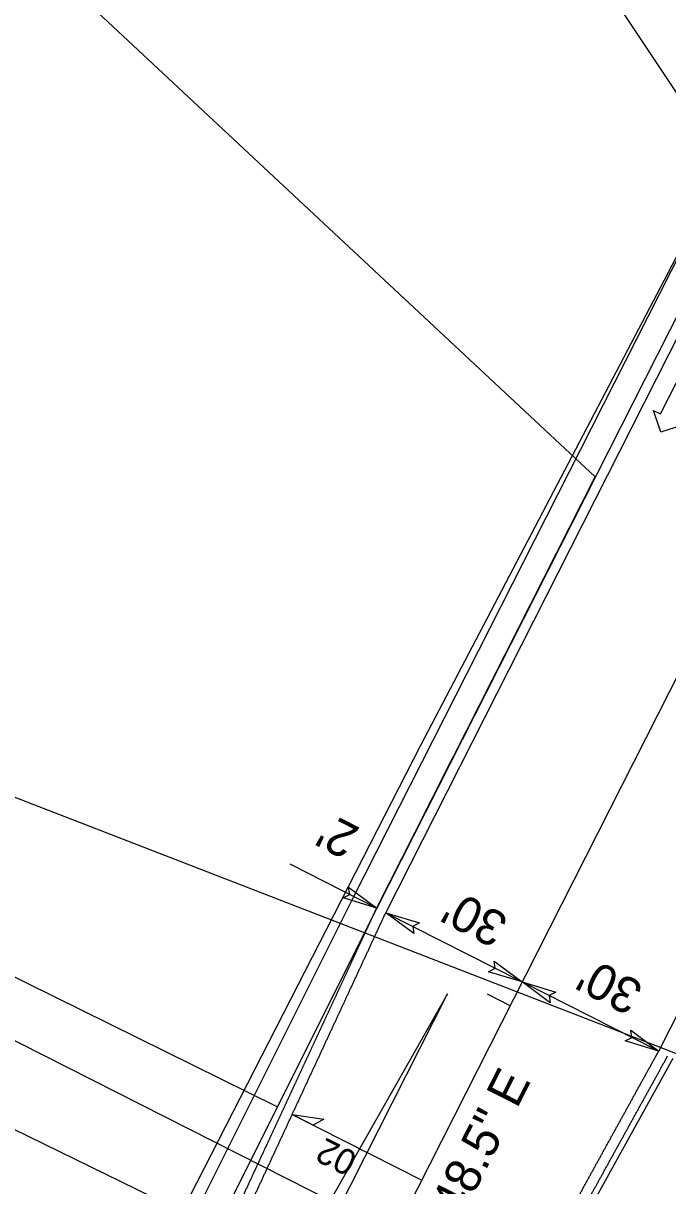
# Model space of a CAD drawing. Extents: x 1974386 to 1979988, y 776712 to 784860.
# Drawn here: x 1977801.6 to 1977928, y 782158.9 to 782386.9 of the extents above; entities that cross this region are included whole.
import ezdxf

# ---------------------------------------------------------------- set-up
doc = ezdxf.new("R2010")
doc.units = 0
for name, color, linetype in [('Prop Conc 2ft 6in Curb and Gutter', 7, 'Continuous'), ('Prop Conc 4in Sidewalk', 7, 'Continuous'), ('Prop Dimension', 7, 'Continuous'), ('Prop Dimension Text', 7, 'Continuous'), ('Prop DSN Text', 7, 'Continuous'), ('Prop EOT', 7, 'Continuous'), ('Prop Guardrail', 7, 'Continuous'), ('Prop Horizontal Alignment', 7, 'Continuous'), ('Prop Horizontal Alignment Direction Label', 7, 'Continuous'), ('Prop Horizontal Alignment Tick Small', 7, 'Continuous'), ('Prop Lane Arrow CELL', 7, 'Continuous'), ('Prop Superelevation  Arrow CELL', 7, 'Continuous'), ('Prop Superelevation Label', 7, 'Continuous'), ('Prop Terminator CELL', 7, 'Continuous'), ('Scratch_Level_1', 7, 'Continuous'), ('Sheet Layout Plan Border', 7, 'Continuous')]:
    doc.layers.add(name, color=color, linetype=linetype)

msp = doc.modelspace()

# ---------------------------------------------------------------- linework, layer by layer
at = {"layer": 'Prop Conc 2ft 6in Curb and Gutter'}
for p, q in [((1977870.83, 782213.26), (1977913.74, 782297.93)), ((1977870.89, 782213.38), (1977885.51, 782242.22))]:
    msp.add_line(p, q, dxfattribs=at)
msp.add_open_spline([(1977849.69, 782167.68), (1977849.78, 782167.88), (1977849.88, 782168.09), (1977849.97, 782168.29), (1977850.07, 782168.5), (1977850.16, 782168.7), (1977850.26, 782168.91), (1977850.36, 782169.12), (1977850.45, 782169.32), (1977850.55, 782169.53), (1977850.64, 782169.73), (1977850.74, 782169.94), (1977850.83, 782170.14), (1977850.93, 782170.35), (1977851.02, 782170.55), (1977851.12, 782170.76), (1977851.21, 782170.97), (1977851.31, 782171.17), (1977851.4, 782171.38), (1977851.5, 782171.58), (1977851.59, 782171.79), (1977851.69, 782171.99), (1977851.79, 782172.2), (1977851.88, 782172.4), (1977851.98, 782172.61), (1977852.07, 782172.82), (1977852.17, 782173.02), (1977852.26, 782173.23), (1977852.36, 782173.43), (1977852.45, 782173.64), (1977852.55, 782173.84), (1977852.64, 782174.05), (1977852.74, 782174.25), (1977852.83, 782174.46), (1977852.93, 782174.67), (1977853.03, 782174.87), (1977853.12, 782175.08), (1977853.22, 782175.28), (1977853.31, 782175.49), (1977853.41, 782175.69), (1977853.5, 782175.9), (1977853.6, 782176.1), (1977853.69, 782176.31), (1977853.79, 782176.52), (1977853.88, 782176.72), (1977853.98, 782176.93), (1977854.07, 782177.13), (1977854.17, 782177.34), (1977854.26, 782177.54), (1977854.36, 782177.75), (1977854.46, 782177.95), (1977854.55, 782178.16), (1977854.65, 782178.37), (1977854.74, 782178.57), (1977854.84, 782178.78), (1977854.93, 782178.98), (1977855.03, 782179.19), (1977855.12, 782179.39), (1977855.22, 782179.6), (1977855.31, 782179.8), (1977855.41, 782180.01), (1977855.5, 782180.22), (1977855.6, 782180.42), (1977855.69, 782180.63), (1977855.79, 782180.83), (1977855.89, 782181.04), (1977855.98, 782181.24), (1977856.08, 782181.45), (1977856.17, 782181.65), (1977856.27, 782181.86), (1977856.36, 782182.07), (1977856.46, 782182.27), (1977856.55, 782182.48), (1977856.65, 782182.68), (1977856.74, 782182.89), (1977856.84, 782183.09), (1977856.93, 782183.3), (1977857.03, 782183.5), (1977857.13, 782183.71), (1977857.22, 782183.92), (1977857.32, 782184.12), (1977857.41, 782184.33), (1977857.51, 782184.53), (1977857.6, 782184.74), (1977857.7, 782184.94), (1977857.79, 782185.15), (1977857.89, 782185.35), (1977857.98, 782185.56), (1977858.08, 782185.77), (1977858.17, 782185.97), (1977858.27, 782186.18), (1977858.36, 782186.38), (1977858.46, 782186.59), (1977858.56, 782186.79), (1977858.65, 782187), (1977858.75, 782187.2), (1977858.84, 782187.41), (1977858.94, 782187.62), (1977859.03, 782187.82), (1977859.13, 782188.03), (1977859.22, 782188.23), (1977859.32, 782188.44), (1977859.41, 782188.64), (1977859.51, 782188.85), (1977859.6, 782189.05), (1977859.7, 782189.26), (1977859.8, 782189.47), (1977859.89, 782189.67), (1977859.99, 782189.88), (1977860.08, 782190.08), (1977860.18, 782190.29), (1977860.27, 782190.49), (1977860.37, 782190.7), (1977860.46, 782190.9), (1977860.56, 782191.11), (1977860.65, 782191.32), (1977860.75, 782191.52), (1977860.84, 782191.73), (1977860.94, 782191.93), (1977861.03, 782192.14), (1977861.13, 782192.34), (1977861.23, 782192.55), (1977861.32, 782192.75), (1977861.42, 782192.96), (1977861.51, 782193.17), (1977861.61, 782193.37), (1977861.7, 782193.58), (1977861.8, 782193.78), (1977861.89, 782193.99), (1977861.99, 782194.19), (1977862.08, 782194.4), (1977862.18, 782194.6), (1977862.27, 782194.81), (1977862.37, 782195.02), (1977862.47, 782195.22), (1977862.56, 782195.43), (1977862.66, 782195.63), (1977862.75, 782195.84), (1977862.85, 782196.04), (1977862.94, 782196.25), (1977863.04, 782196.45), (1977863.13, 782196.66), (1977863.23, 782196.87), (1977863.32, 782197.07), (1977863.42, 782197.28), (1977863.51, 782197.48), (1977863.61, 782197.69), (1977863.7, 782197.89), (1977863.8, 782198.1), (1977863.9, 782198.3), (1977863.99, 782198.51), (1977864.09, 782198.72), (1977864.18, 782198.92), (1977864.28, 782199.13), (1977864.37, 782199.33), (1977864.47, 782199.54), (1977864.56, 782199.74), (1977864.66, 782199.95), (1977864.75, 782200.15), (1977864.85, 782200.36), (1977864.94, 782200.57), (1977865.04, 782200.77), (1977865.14, 782200.98), (1977865.23, 782201.18), (1977865.33, 782201.39), (1977865.42, 782201.59), (1977865.52, 782201.8), (1977865.61, 782202), (1977865.71, 782202.21), (1977865.8, 782202.42), (1977865.9, 782202.62), (1977865.99, 782202.83), (1977866.09, 782203.03), (1977866.18, 782203.24), (1977866.28, 782203.44), (1977866.37, 782203.65), (1977866.47, 782203.85), (1977866.57, 782204.06), (1977866.66, 782204.27), (1977866.76, 782204.47), (1977866.85, 782204.68), (1977866.95, 782204.88), (1977867.04, 782205.09), (1977867.14, 782205.29), (1977867.23, 782205.5), (1977867.33, 782205.7), (1977867.42, 782205.91), (1977867.52, 782206.12), (1977867.61, 782206.32), (1977867.71, 782206.53), (1977867.81, 782206.73), (1977867.9, 782206.94), (1977868, 782207.14), (1977868.09, 782207.35), (1977868.19, 782207.55), (1977868.28, 782207.76), (1977868.38, 782207.97), (1977868.47, 782208.17), (1977868.57, 782208.38), (1977868.66, 782208.58), (1977868.76, 782208.79), (1977868.85, 782208.99), (1977868.95, 782209.2), (1977869.04, 782209.4), (1977869.14, 782209.61), (1977869.24, 782209.82), (1977869.33, 782210.02), (1977869.43, 782210.23), (1977869.52, 782210.43), (1977869.62, 782210.64), (1977869.71, 782210.84), (1977869.81, 782211.05), (1977869.9, 782211.25), (1977870, 782211.46), (1977870.09, 782211.67), (1977870.19, 782211.87), (1977870.28, 782212.08), (1977870.46, 782212.45), (1977870.63, 782212.83), (1977870.81, 782213.21)], degree=3, dxfattribs=at)
for points in [[(1977903.76, 782140.54), (1977904.09, 782141.13), (1977904.41, 782141.73), (1977904.74, 782142.32), (1977905.07, 782142.91), (1977905.39, 782143.5), (1977905.72, 782144.1), (1977906.05, 782144.69), (1977906.37, 782145.28), (1977906.7, 782145.87), (1977907.03, 782146.46), (1977907.35, 782147.06), (1977907.68, 782147.65), (1977908.01, 782148.24), (1977908.33, 782148.83), (1977908.66, 782149.43), (1977908.99, 782150.02), (1977909.31, 782150.61), (1977909.64, 782151.2), (1977909.97, 782151.8), (1977910.29, 782152.39), (1977910.62, 782152.98), (1977910.95, 782153.57), (1977911.27, 782154.16), (1977911.6, 782154.76), (1977911.93, 782155.35), (1977912.25, 782155.94), (1977912.58, 782156.53), (1977912.91, 782157.13), (1977913.23, 782157.72), (1977913.56, 782158.31), (1977913.89, 782158.9), (1977914.22, 782159.5), (1977914.54, 782160.09), (1977914.87, 782160.68), (1977915.2, 782161.27), (1977915.52, 782161.87), (1977915.85, 782162.46), (1977916.18, 782163.05), (1977916.5, 782163.64), (1977916.83, 782164.23), (1977917.16, 782164.83), (1977917.48, 782165.42), (1977917.81, 782166.01), (1977918.14, 782166.6), (1977918.46, 782167.2), (1977918.79, 782167.79), (1977919.12, 782168.38), (1977919.44, 782168.97), (1977919.77, 782169.57), (1977920.1, 782170.16), (1977920.42, 782170.75), (1977920.75, 782171.34), (1977921.08, 782171.94), (1977921.4, 782172.53), (1977921.73, 782173.12), (1977922.06, 782173.71), (1977922.38, 782174.3), (1977922.71, 782174.9), (1977923.04, 782175.49), (1977923.36, 782176.08), (1977923.69, 782176.67), (1977924.02, 782177.27), (1977924.34, 782177.86), (1977924.67, 782178.45), (1977925, 782179.04), (1977925.33, 782179.64), (1977925.65, 782180.23), (1977925.98, 782180.82), (1977926.31, 782181.41), (1977926.63, 782182), (1977926.96, 782182.6), (1977927.29, 782183.19), (1977927.94, 782184.37)], [(1977828.52, 782122.04), (1977828.8, 782122.66), (1977829.09, 782123.28), (1977829.38, 782123.89), (1977829.66, 782124.51), (1977829.95, 782125.13), (1977830.24, 782125.74), (1977830.52, 782126.36), (1977830.81, 782126.98), (1977831.09, 782127.59), (1977831.38, 782128.21), (1977831.67, 782128.83), (1977831.95, 782129.44), (1977832.24, 782130.06), (1977832.52, 782130.68), (1977832.81, 782131.29), (1977833.1, 782131.91), (1977833.38, 782132.53), (1977833.67, 782133.14), (1977833.95, 782133.76), (1977834.24, 782134.38), (1977834.53, 782134.99), (1977834.81, 782135.61), (1977835.1, 782136.23), (1977835.38, 782136.84), (1977835.67, 782137.46), (1977835.96, 782138.08), (1977836.24, 782138.69), (1977836.53, 782139.31), (1977836.81, 782139.93), (1977837.1, 782140.54), (1977837.39, 782141.16), (1977837.67, 782141.78), (1977837.96, 782142.39), (1977838.24, 782143.01), (1977838.53, 782143.63), (1977838.82, 782144.24), (1977839.1, 782144.86), (1977839.39, 782145.48), (1977839.68, 782146.09), (1977839.96, 782146.71), (1977840.25, 782147.33), (1977840.53, 782147.94), (1977840.82, 782148.56), (1977841.11, 782149.18), (1977841.39, 782149.79), (1977841.68, 782150.41), (1977841.96, 782151.03), (1977842.25, 782151.64), (1977842.54, 782152.26), (1977842.82, 782152.88), (1977843.11, 782153.49), (1977843.39, 782154.11), (1977843.68, 782154.73), (1977843.97, 782155.34), (1977844.25, 782155.96), (1977844.54, 782156.58), (1977844.82, 782157.19), (1977845.11, 782157.81), (1977845.4, 782158.43), (1977845.68, 782159.04), (1977845.97, 782159.66), (1977846.25, 782160.28), (1977846.54, 782160.89), (1977846.83, 782161.51), (1977847.11, 782162.13), (1977847.4, 782162.74), (1977847.69, 782163.36), (1977847.97, 782163.98), (1977848.26, 782164.59), (1977848.54, 782165.21), (1977848.83, 782165.83), (1977849.12, 782166.44), (1977849.4, 782167.06), (1977849.69, 782167.68)]]:
    msp.add_spline(points, degree=3, dxfattribs=at)
at = {"layer": 'Prop Conc 4in Sidewalk'}
for p, q in [((1977866.43, 782215.64), (1977942.22, 782365.15)), ((1977946.67, 782362.89), (1977870.89, 782213.38)), ((1977798.87, 782080.62), (1977866.43, 782215.64)), ((1977870.89, 782213.38), (1977803.34, 782078.38))]:
    msp.add_line(p, q, dxfattribs=at)
at = {"layer": 'Prop Dimension'}
for p, q in [((1977853.84, 782222.02), (1977870.89, 782213.38)), ((1977872.67, 782212.47), (1977899.43, 782198.9)), ((1977780.96, 782209.18), (1977851.33, 782174.46)), ((1977926.19, 782185.34), (1977899.43, 782198.9)), ((1977769, 782184.95), (1977840.09, 782150.35))]:
    msp.add_line(p, q, dxfattribs=at)
at = {"layer": 'Prop DSN Text'}
for p, q in [((1977933.68, 782367.22), (1977839.3, 782509.19)), ((1977913.74, 782297.93), (1977815.26, 782389.86))]:
    msp.add_line(p, q, dxfattribs=at)
at = {"layer": 'Prop EOT'}
for p, q in [((1977872.67, 782212.47), (1977948.46, 782361.98)), ((1977926.19, 782185.34), (1978002.32, 782335.53))]:
    msp.add_line(p, q, dxfattribs=at)
for points in [[(1977851.63, 782167.08), (1977851.91, 782167.69), (1977852.19, 782168.31), (1977852.48, 782168.92), (1977852.76, 782169.53), (1977853.05, 782170.15), (1977853.33, 782170.76), (1977853.62, 782171.37), (1977853.9, 782171.99), (1977854.18, 782172.6), (1977854.47, 782173.21), (1977854.75, 782173.83), (1977855.04, 782174.44), (1977855.32, 782175.05), (1977855.61, 782175.67), (1977855.89, 782176.28), (1977856.18, 782176.89), (1977856.46, 782177.51), (1977856.74, 782178.12), (1977857.03, 782178.73), (1977857.31, 782179.35), (1977857.6, 782179.96), (1977857.88, 782180.57), (1977858.17, 782181.19), (1977858.45, 782181.8), (1977858.74, 782182.41), (1977859.02, 782183.03), (1977859.3, 782183.64), (1977859.59, 782184.25), (1977859.87, 782184.87), (1977860.16, 782185.48), (1977860.44, 782186.09), (1977860.73, 782186.71), (1977861.01, 782187.32), (1977861.29, 782187.93), (1977861.58, 782188.55), (1977861.86, 782189.16), (1977862.15, 782189.77), (1977862.43, 782190.39), (1977862.72, 782191), (1977863, 782191.61), (1977863.29, 782192.23), (1977863.57, 782192.84), (1977863.85, 782193.45), (1977864.14, 782194.07), (1977864.42, 782194.68), (1977864.71, 782195.29), (1977864.99, 782195.91), (1977865.28, 782196.52), (1977865.56, 782197.13), (1977865.85, 782197.75), (1977866.13, 782198.36), (1977866.41, 782198.97), (1977866.7, 782199.59), (1977866.98, 782200.2), (1977867.27, 782200.81), (1977867.55, 782201.43), (1977867.84, 782202.04), (1977868.12, 782202.65), (1977868.4, 782203.27), (1977868.69, 782203.88), (1977868.97, 782204.49), (1977869.26, 782205.11), (1977869.54, 782205.72), (1977869.83, 782206.33), (1977870.11, 782206.95), (1977870.4, 782207.56), (1977870.68, 782208.17), (1977870.96, 782208.79), (1977871.25, 782209.4), (1977871.53, 782210.01), (1977871.82, 782210.63), (1977872.1, 782211.24), (1977872.67, 782212.47)], [(1977902.02, 782141.53), (1977902.35, 782142.13), (1977902.67, 782142.72), (1977903, 782143.31), (1977903.33, 782143.9), (1977903.65, 782144.49), (1977903.98, 782145.09), (1977904.31, 782145.68), (1977904.63, 782146.27), (1977904.96, 782146.86), (1977905.29, 782147.45), (1977905.61, 782148.05), (1977905.94, 782148.64), (1977906.27, 782149.23), (1977906.59, 782149.82), (1977906.92, 782150.41), (1977907.25, 782151.01), (1977907.57, 782151.6), (1977907.9, 782152.19), (1977908.23, 782152.78), (1977908.55, 782153.37), (1977908.88, 782153.97), (1977909.21, 782154.56), (1977909.53, 782155.15), (1977909.86, 782155.74), (1977910.19, 782156.33), (1977910.51, 782156.93), (1977910.84, 782157.52), (1977911.17, 782158.11), (1977911.49, 782158.7), (1977911.82, 782159.29), (1977912.14, 782159.89), (1977912.47, 782160.48), (1977912.8, 782161.07), (1977913.12, 782161.66), (1977913.45, 782162.25), (1977913.78, 782162.85), (1977914.1, 782163.44), (1977914.43, 782164.03), (1977914.76, 782164.62), (1977915.08, 782165.21), (1977915.41, 782165.81), (1977915.74, 782166.4), (1977916.06, 782166.99), (1977916.39, 782167.58), (1977916.72, 782168.17), (1977917.04, 782168.77), (1977917.37, 782169.36), (1977917.7, 782169.95), (1977918.02, 782170.54), (1977918.35, 782171.13), (1977918.68, 782171.72), (1977919, 782172.32), (1977919.33, 782172.91), (1977919.66, 782173.5), (1977919.98, 782174.09), (1977920.31, 782174.68), (1977920.64, 782175.28), (1977920.96, 782175.87), (1977921.29, 782176.46), (1977921.62, 782177.05), (1977921.94, 782177.64), (1977922.27, 782178.24), (1977922.6, 782178.83), (1977922.92, 782179.42), (1977923.25, 782180.01), (1977923.58, 782180.6), (1977923.9, 782181.2), (1977924.23, 782181.79), (1977924.56, 782182.38), (1977924.88, 782182.97), (1977925.21, 782183.56), (1977925.53, 782184.16), (1977926.19, 782185.34)], [(1977830.58, 782121.69), (1977830.86, 782122.3), (1977831.15, 782122.92), (1977831.43, 782123.53), (1977831.72, 782124.14), (1977832, 782124.76), (1977832.29, 782125.37), (1977832.57, 782125.98), (1977832.86, 782126.6), (1977833.14, 782127.21), (1977833.42, 782127.82), (1977833.71, 782128.44), (1977833.99, 782129.05), (1977834.28, 782129.66), (1977834.56, 782130.28), (1977834.85, 782130.89), (1977835.13, 782131.5), (1977835.41, 782132.12), (1977835.7, 782132.73), (1977835.98, 782133.34), (1977836.27, 782133.96), (1977836.55, 782134.57), (1977836.84, 782135.18), (1977837.12, 782135.8), (1977837.41, 782136.41), (1977837.69, 782137.02), (1977837.97, 782137.64), (1977838.26, 782138.25), (1977838.54, 782138.86), (1977838.83, 782139.48), (1977839.11, 782140.09), (1977839.4, 782140.7), (1977839.68, 782141.32), (1977839.97, 782141.93), (1977840.25, 782142.54), (1977840.53, 782143.16), (1977840.82, 782143.77), (1977841.1, 782144.38), (1977841.39, 782145), (1977841.67, 782145.61), (1977841.96, 782146.22), (1977842.24, 782146.84), (1977842.52, 782147.45), (1977842.81, 782148.06), (1977843.09, 782148.68), (1977843.38, 782149.29), (1977843.66, 782149.9), (1977843.95, 782150.52), (1977844.23, 782151.13), (1977844.52, 782151.74), (1977844.8, 782152.36), (1977845.08, 782152.97), (1977845.37, 782153.59), (1977845.65, 782154.2), (1977845.94, 782154.81), (1977846.22, 782155.43), (1977846.51, 782156.04), (1977846.79, 782156.65), (1977847.08, 782157.27), (1977847.36, 782157.88), (1977847.64, 782158.49), (1977847.93, 782159.11), (1977848.21, 782159.72), (1977848.5, 782160.33), (1977848.78, 782160.95), (1977849.07, 782161.56), (1977849.35, 782162.17), (1977849.63, 782162.79), (1977849.92, 782163.4), (1977850.2, 782164.01), (1977850.49, 782164.63), (1977850.77, 782165.24), (1977851.06, 782165.85), (1977851.34, 782166.47), (1977851.63, 782167.08)]]:
    msp.add_spline(points, degree=3, dxfattribs=at)
at = {"layer": 'Prop Guardrail'}
for p, q in [((1977939.06, 782359.12), (1977879.49, 782245.27)), ((1977879.49, 782245.27), (1977832.76, 782153.94)), ((1977862.8, 782064.15), (1977928.99, 782183.92))]:
    msp.add_line(p, q, dxfattribs=at)
at = {"layer": 'Prop Horizontal Alignment'}
msp.add_line((1977839.03, 782079.75), (1978119.82, 782633.69), dxfattribs=at)
at = {"layer": 'Prop Horizontal Alignment Tick Small'}
msp.add_line((1977897.05, 782194.2), (1977892.59, 782196.46), dxfattribs=at)
at = {"layer": 'Prop Lane Arrow CELL'}
for p, q in [((1977926.53, 782310.25), (1977932.88, 782322.72)), ((1977926.61, 782306.67), (1977925.19, 782310.93)), ((1977925.19, 782310.93), (1977926.53, 782310.25)), ((1977930.8, 782308.07), (1977926.61, 782306.67))]:
    msp.add_line(p, q, dxfattribs=at)
at = {"layer": 'Prop Superelevation  Arrow CELL'}
msp.add_lwpolyline([(1977854.3, 782172.87), (1977860.56, 782171.95), (1977858.43, 782170.78)], close=True, dxfattribs=at)
at = {"layer": 'Prop Superelevation Label'}
msp.add_line((1977854.3, 782172.87), (1977879.71, 782160), dxfattribs=at)
at = {"layer": 'Prop Terminator CELL'}
for points in [[(1977865.39, 782217.46), (1977870.89, 782213.38), (1977864.29, 782215.37), (1977865.6, 782216.05)], [(1977878.17, 782208.38), (1977872.67, 782212.47), (1977879.27, 782210.47), (1977877.96, 782209.79)], [(1977893.93, 782202.99), (1977899.43, 782198.9), (1977892.83, 782200.9), (1977894.14, 782201.58)], [(1977904.92, 782194.82), (1977899.43, 782198.9), (1977906.03, 782196.91), (1977904.71, 782196.23)], [(1977920.69, 782189.43), (1977926.19, 782185.34), (1977919.59, 782187.34), (1977920.9, 782188.02)]]:
    msp.add_lwpolyline(points, close=True, dxfattribs=at)
at = {"layer": 'Scratch_Level_1'}
for p, q in [((1977884.79, 782196.56), (1977671.06, 781820.03)), ((1977828.33, 782085.17), (1977884.79, 782196.56))]:
    msp.add_line(p, q, dxfattribs=at)
at = {"layer": 'Sheet Layout Plan Border'}
for points in [[(1978342.72, 781912.24), (1978974.34, 783158.3), (1978974.34, 783158.3), (1978037.78, 783633.03), (1978037.78, 783633.03), (1977406.16, 782386.97), (1977406.16, 782386.97)], [(1977881.86, 780701.89), (1978387.67, 782007.32), (1977408.59, 782386.68), (1976902.78, 781081.25)]]:
    msp.add_lwpolyline(points, close=True, dxfattribs=at)

# ---------------------------------------------------------------- texts
at = {"layer": 'Prop Dimension Text'}
for s, p in [("2'", (1977867.88, 782228.96)), ("30'", (1977897.09, 782211.59)), ("30'", (1977923.55, 782198.35))]:
    msp.add_text(s, height=7, rotation=152.7847, dxfattribs=at).set_placement(p)
at = {"layer": 'Prop Horizontal Alignment Direction Label'}
msp.add_text('N 26%%d 52\' 48.5" E', height=7, rotation=63.1199, dxfattribs=at).set_placement((1977868.96, 782115.86))
at = {"layer": 'Prop Superelevation Label'}
msp.add_text('02', height=5, rotation=153.1199, dxfattribs=at).set_placement((1977867.41, 782165.12))

doc.saveas('drawing.dxf')
